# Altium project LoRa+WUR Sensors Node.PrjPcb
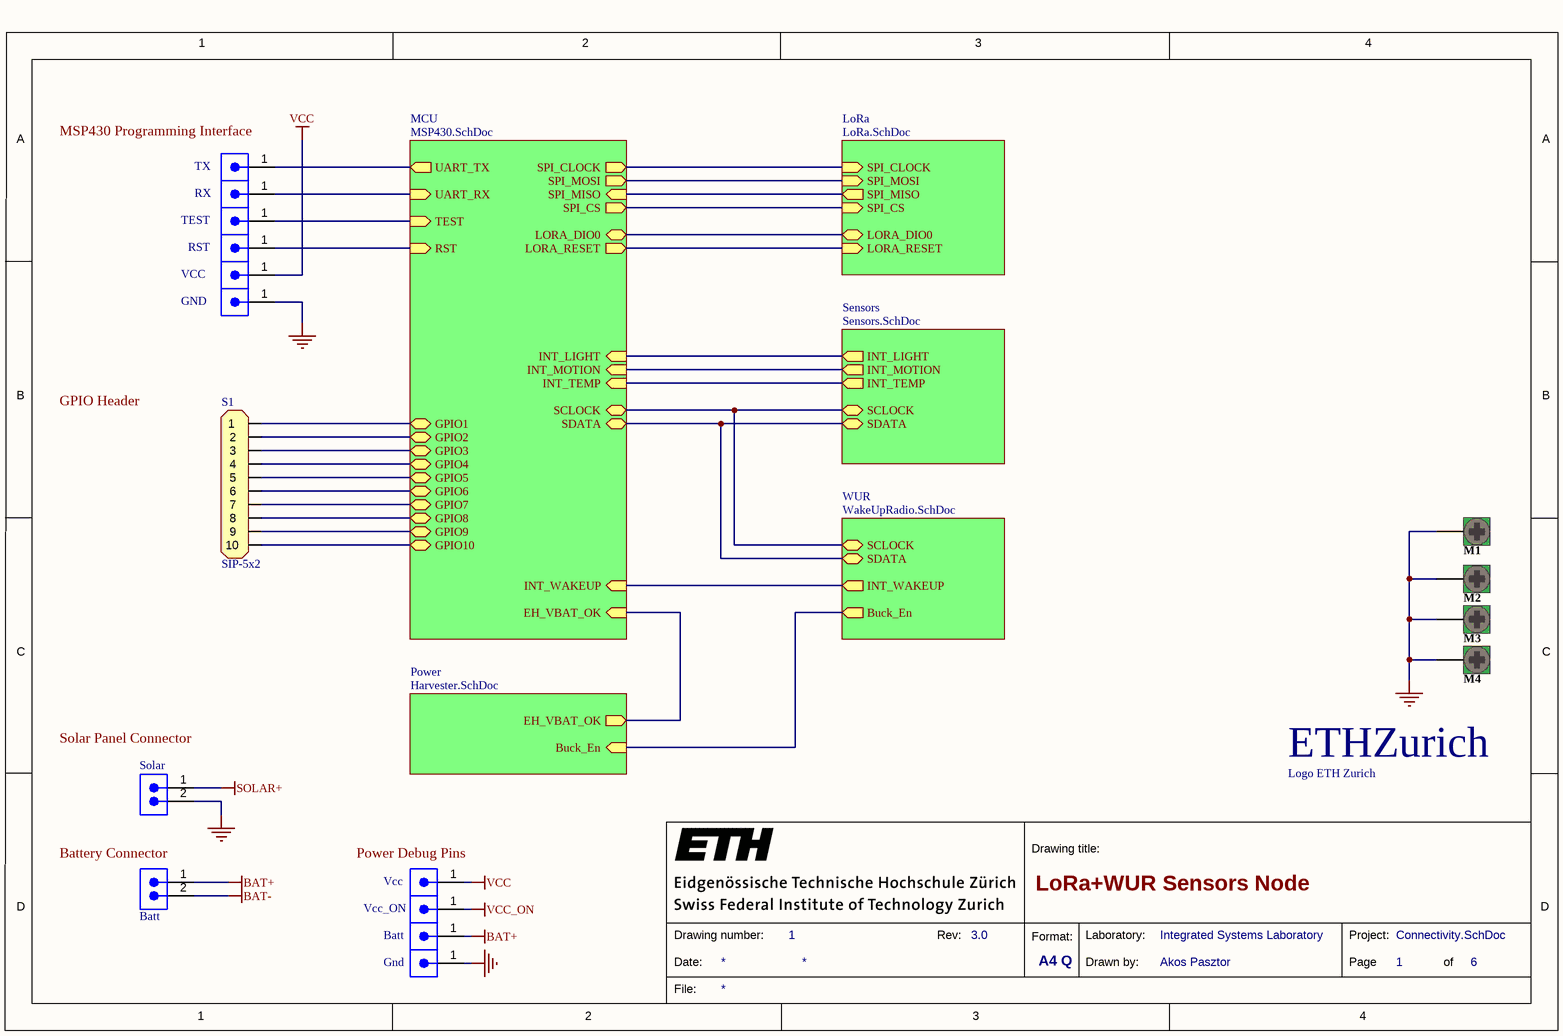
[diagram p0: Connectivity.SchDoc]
Author: Akos Pasztor; CompanyName: ETH Zurich; DrawnBy: Akos Pasztor; Engineer: Akos Pasztor; Organization: Integrated Systems Laboratory; Revision: 3.0; Title: LoRa+WUR Sensors Node
6 sheets, 127 parts. Net scope: hierarchical (ports join the sheet entries above them; power ports are global).
Board file: PCB.PcbDoc
Sheets:
  Connectivity.SchDoc
    MCU = MSP430.SchDoc
    Power = Harvester.SchDoc
    Sensors = Sensors.SchDoc
    WUR = WakeUpRadio.SchDoc
    LoRa = LoRa.SchDoc

## Sheet Connectivity.SchDoc: LoRa+WUR Sensors Node
size A4; Author: Akos Pasztor; CompanyName: ETH Zurich; DrawnBy: Akos Pasztor; Engineer: Akos Pasztor; Organization: Integrated Systems Laboratory; DocumentNumber: 1; Revision: 3.0; SheetNumber: 1; SheetTotal: 6

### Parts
A1  Logo ETH Zurich  [eth-zurich_3mm]  (no BOM)
M1  Mounting Hole  [Hole M3]  (value not drawn)  (no BOM)
M2  Mounting Hole  [Hole M3]  (value not drawn)  (no BOM)
M3  Mounting Hole  [Hole M3]  (value not drawn)  (no BOM)
M4  Mounting Hole  [Hole M3]  (value not drawn)  (no BOM)
S1  SIP-5x2  [SIP-5x2]
X1  TX  [TSW-150-07-G-S]
X2  RX  [TSW-150-07-G-S]
X3  TEST  [TSW-150-07-G-S]
X4  RST  [TSW-150-07-G-S]
X5  VCC  [TSW-150-07-G-S]
X6  GND  [TSW-150-07-G-S]
X7  Batt  [Pin Header, 1x2]
X8  Solar  [Pin Header, 1x2]
X18  Vcc  [TSW-150-07-G-S]
X25  Vcc_ON  [TSW-150-07-G-S]
X27  Batt  [TSW-150-07-G-S]
X28  Gnd  [TSW-150-07-G-S]

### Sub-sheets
LoRa = LoRa.SchDoc: SPI_CLOCK (in), SPI_MOSI (in), SPI_MISO (out), LORA_DIO0 (bidir), LORA_RESET (in), SPI_CS (in)
MCU = MSP430.SchDoc: SPI_CLOCK (out), SPI_MOSI (out), SPI_MISO (in), LORA_DIO0 (bidir), LORA_RESET (out), SPI_CS (out), INT_LIGHT (in), INT_MOTION (in), INT_TEMP (in), SCLOCK (bidir), SDATA (bidir), INT_WAKEUP (in), EH_VBAT_OK (in), UART_TX (out), UART_RX (in), TEST (in), RST (in), GPIO1 (bidir), GPIO2 (bidir), GPIO3 (bidir), GPIO4 (bidir), GPIO5 (bidir), GPIO6 (bidir), GPIO7 (bidir), GPIO8 (bidir), GPIO9 (bidir), GPIO10 (bidir)
Power = Harvester.SchDoc: Buck_En (in), EH_VBAT_OK (out)
Sensors = Sensors.SchDoc: INT_LIGHT (out), INT_MOTION (out), INT_TEMP (out), SCLOCK (bidir), SDATA (bidir)
WUR = WakeUpRadio.SchDoc: SCLOCK (bidir), SDATA (bidir), INT_WAKEUP (out), Buck_En (out)

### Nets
BAT+: X7.1 X27.1
BAT-: X7.2
GND: M1.1 M2.1 M3.1 M4.1 X6.1 X8.2 X28.1
SOLAR+: X8.1
VCC: X5.1 X18.1
VCC_ON: X25.1
Buck_En: sheet Power/Buck_En, sheet WUR/Buck_En
LORA_DIO0: sheet MCU/LORA_DIO0, sheet LoRa/LORA_DIO0
LORA_RESET: sheet MCU/LORA_RESET, sheet LoRa/LORA_RESET
SCLK: sheet MCU/SCLOCK, sheet Sensors/SCLOCK, sheet WUR/SCLOCK
SDATA: sheet MCU/SDATA, sheet Sensors/SDATA, sheet WUR/SDATA
SI: sheet MCU/INT_WAKEUP, sheet WUR/INT_WAKEUP
NetJ1_1: sheet MCU/EH_VBAT_OK, sheet Power/EH_VBAT_OK
NetR17_1: sheet MCU/INT_MOTION, sheet Sensors/INT_MOTION
NetR18_1: sheet MCU/INT_LIGHT, sheet Sensors/INT_LIGHT
NetR22_2: sheet MCU/INT_TEMP, sheet Sensors/INT_TEMP
NetS1_1: S1.1 ; sheet MCU/GPIO1
NetS1_2: S1.2 ; sheet MCU/GPIO2
NetS1_3: S1.3 ; sheet MCU/GPIO3
NetS1_4: S1.4 ; sheet MCU/GPIO4
NetS1_5: S1.5 ; sheet MCU/GPIO5
NetS1_6: S1.6 ; sheet MCU/GPIO6
NetS1_7: S1.7 ; sheet MCU/GPIO7
NetS1_8: S1.8 ; sheet MCU/GPIO8
NetS1_9: S1.9 ; sheet MCU/GPIO9
NetS1_10: S1.10 ; sheet MCU/GPIO10
NetU2_4: sheet MCU/SPI_CS, sheet LoRa/SPI_CS
NetU2_11: sheet MCU/SPI_CLOCK, sheet LoRa/SPI_CLOCK
NetU2_20: X1.1 ; sheet MCU/UART_TX
NetU2_21: X2.1 ; sheet MCU/UART_RX
NetU2_22: X3.1 ; sheet MCU/TEST
NetU2_23: X4.1 ; sheet MCU/RST
NetU2_24: sheet MCU/SPI_MOSI, sheet LoRa/SPI_MOSI
NetU2_25: sheet MCU/SPI_MISO, sheet LoRa/SPI_MISO

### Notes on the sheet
- (near X1) MSP430 Programming Interface
- GPIO Header
- (near X8) Solar Panel Connector
- (near X7) Battery Connector
- (near X18) Power Debug Pins

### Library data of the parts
A1 = CMP-00038-1
M1-M4 = CMP-00023-1: Mounting Hole, 7.2mm pad, 3.2mm plated hole
S1 = SIP-5x2: SIP-5x2 2.54mm 2-row; Pitch: 100mil (2.54mm)
X1-X6 = CMP-00008-1: Terminal Assembly, 1 Pin, Vertical, 2.54mm Pitch, Male; Manufacturer: Samtec
X7 X8 = CMP-00100-1: 2 CONTACT(S), MALE, STRAIGHT TWO PART BOARD CONNECTOR, SOLDER, 2.54mm, 1x2; Manufacturer: Amphenol FCI; Manufacturer Part Number: 68000-102HLF; Connector Type: Header, Unshrouded; Number of Positions: 2; Number of Positions Loaded: All; Pitch: 0.100" (2.54mm)
X18 X25 X27 X28 = CMP-00008-2: Conn Unshrouded Header HDR 1 POS Vertical Solder ST Thru-Hole; Manufacturer: Amphenol FCI; Manufacturer Part Number: 68001-101HLF; Connector Type: Header, Unshrouded; Number of Positions: 1; Number of Positions Loaded: All

## Sheet MSP430.SchDoc: LoRa+WUR Sensors Node
size A4; Author: Akos Pasztor; CompanyName: ETH Zurich; DrawnBy: Akos Pasztor; Engineer: Akos Pasztor; Organization: Integrated Systems Laboratory; DocumentNumber: 1; Revision: 3.0; SheetNumber: 2; SheetTotal: 6
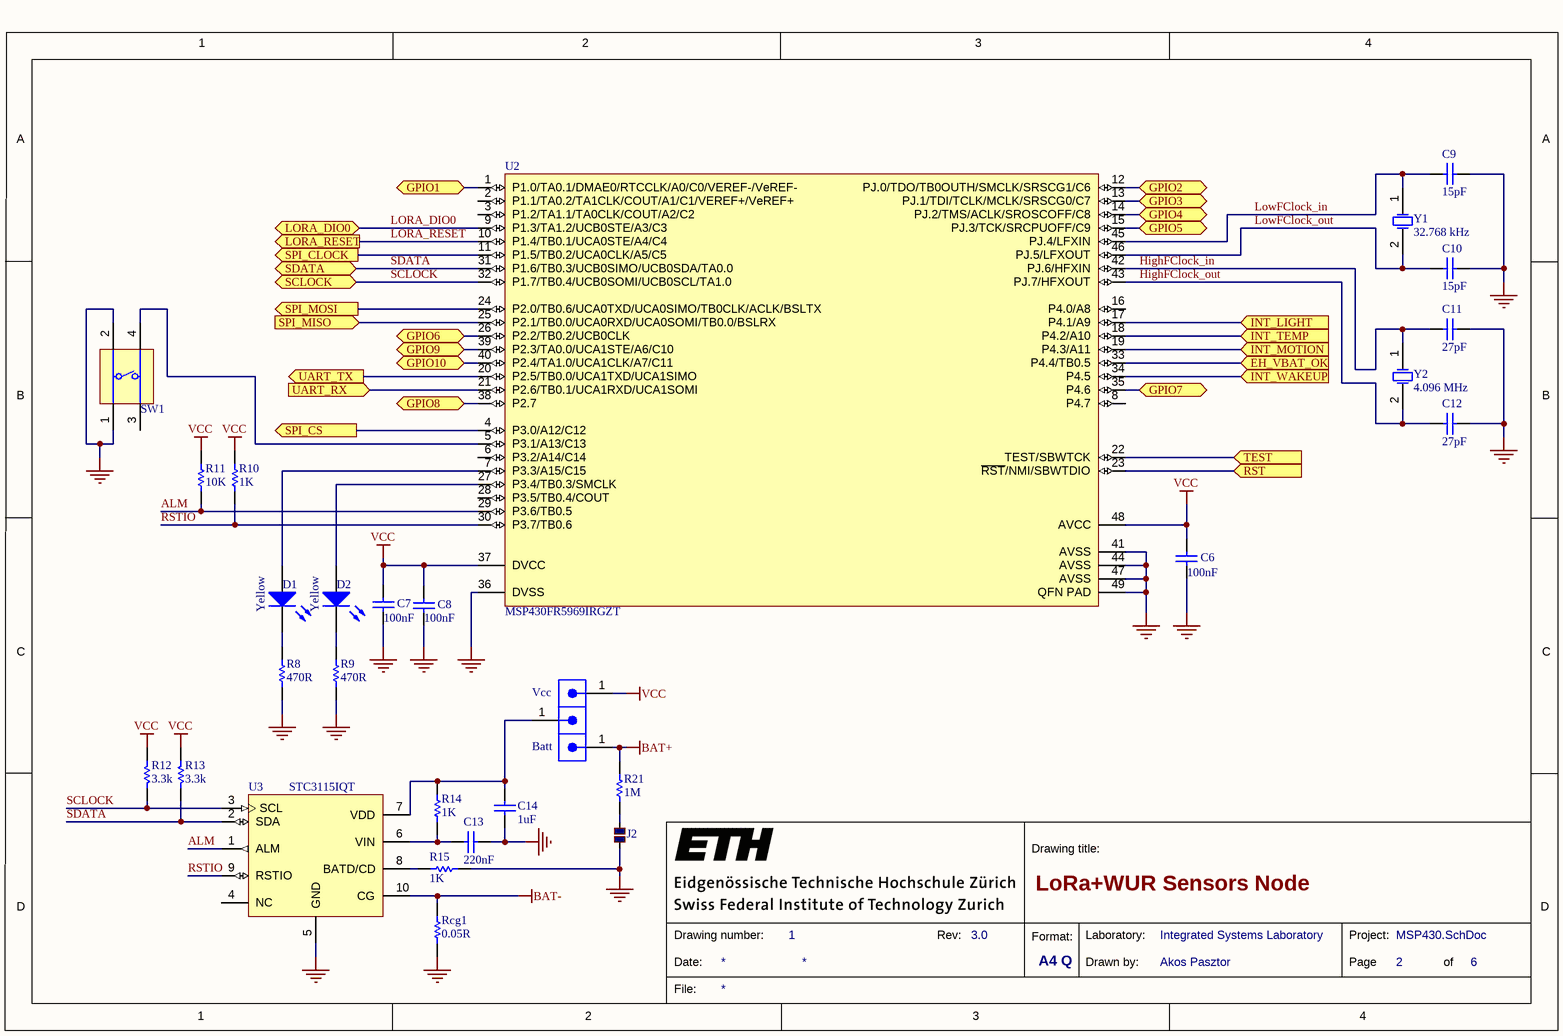
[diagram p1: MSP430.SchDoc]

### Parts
C6  value 100nF  [CAPC0805(2012)145_N]  (hidden comment: CAP 100nF 16V 0805(2012))
C7  value 100nF  [CAPC0805(2012)145_N]  (hidden comment: CAP 100nF 16V 0805(2012))
C8  value 100nF  [CAPC0805(2012)145_N]  (hidden comment: CAP 100nF 16V 0805(2012))
C9  value 15pF  [CAPC0402(1005)60_N]  (hidden comment: CAP 15pF 25V 0402(1005))
C10  value 15pF  [CAPC0402(1005)60_N]  (hidden comment: CAP 15pF 25V 0402(1005))
C11  value 27pF  [CAPC0805(2012)100_N]  (hidden comment: CAP 27pF 10V 0805(2012))
C12  value 27pF  [CAPC0805(2012)100_N]  (hidden comment: CAP 27pF 10V 0805(2012))
C13  value 220nF  [CAPC0805(2012)145_N]  (hidden comment: CAP 220nF 16V 0805(2012))
C14  value 1uF  [CAPC0805(2012)145_N]  (hidden comment: CAP 1uF 16V 0805(2012))
D1  Color: Yellow  [0805_A]  (hidden comment: 150080YS75000)
D2  Color: Yellow  [0805_A]  (hidden comment: 150080YS75000)
J2  Solder Jumper  [Small Solder Jumper]  (value not drawn)
R8  470R  [RESC0603(1608)_N]
R9  470R  [RESC0603(1608)_N]
R10  value 1K  [RESC0805(2012)_N]  (hidden comment: 1K 1% 0805(2012))
R11  value 10K  [RESC0805(2012)_N]  (hidden comment: 10K 1% 0805(2012))
R12  value 3.3k  [RESC0805(2012)_N]  (hidden comment: 3K3 1% 0805(2012))
R13  value 3.3k  [RESC0805(2012)_N]  (hidden comment: 3K3 1% 0805(2012))
R14  value 1K  [RESC0805(2012)_N]  (hidden comment: 1K 1% 0805(2012))
R15  value 1K  [RESC0805(2012)_N]  (hidden comment: 1K 1% 0805(2012))
R21  1M  [RESC0603(1608)_M]
Rcg1  value 0.05R  [RESC0805(2012)_N]  (hidden comment: UCR10EVHFSR050)
SW1  ADTSM62RVTR  [SW_DTSM-62N]  (value not drawn)
U2  MSP430FR5969IRGZT  [QFN-48-7x7-4.1x4.1_N]
U3  STC3115IQT  [SON50P200X60-10N]
X21  Vcc  [TSW-150-07-G-S]
X22  (no value)  [TSW-150-07-G-S]
X23  Batt  [TSW-150-07-G-S]
Y1  Frequency: 32.768 kHz  [ABRA-ABS07-2_V]  (hidden comment: ABS07-32.768KHz-T)
Y2  Frequency: 4.096 MHz  [ABRA-ABLS2-2_V]  (hidden comment: ABLS2-4.096MHZ-D4Y-T)

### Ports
EH_VBAT_OK (in), GPIO1 (bidir), GPIO2 (bidir), GPIO3 (bidir), GPIO4 (bidir), GPIO5 (bidir), GPIO6 (bidir), GPIO7 (bidir), GPIO8 (bidir), GPIO9 (bidir), GPIO10 (bidir), INT_LIGHT (in), INT_MOTION (in), INT_TEMP (in), INT_WAKEUP (in), LORA_DIO0 (bidir), LORA_RESET (out), RST (in), SCLOCK (bidir), SDATA (bidir), SPI_CLOCK (out), SPI_CS (out), SPI_MISO (in), SPI_MOSI (out), TEST (in), UART_RX (in), UART_TX (out)

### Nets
BAT+: R21.1 X23.1
BAT-: Rcg1.2 U3.10(CG)
GND: C6.1 C7.1 C8.1 C9.2 C10.2 C11.1 C12.1 C13.2 C14.1 J2.2 R8.2 R9.2 R15.1 Rcg1.1 SW1.1(T1) SW1.2(T2) U2.36(DVSS) U2.41(AVSS) U2.44(AVSS) U2.47(AVSS) U2.49(QFN_PAD) U3.5(GND)
VCC: C6.2 C7.2 C8.2 R10.1 R11.1 R12.2 R13.2 U2.37(DVCC) U2.48(AVCC) X21.1
ALM: R11.2 U2.29(P3.6/TB0.5) U3.1(ALM)
HighFClock_in: C11.2 U2.42(PJ.6/HFXIN) Y2.1(X1)
HighFClock_out: C12.2 U2.43(PJ.7/HFXOUT) Y2.2(X2)
LORA_DIO0: U2.9(P1.3/TA1.2/UCB0STE/A3/C3) ; port LORA_DIO0
LORA_RESET: U2.10(P1.4/TB0.1/UCA0STE/A4/C4) ; port LORA_RESET
LowFClock_in: C9.1 U2.45(PJ.4/LFXIN) Y1.1(X1)
LowFClock_out: C10.1 U2.46(PJ.5/LFXOUT) Y1.2(X2)
RSTIO: R10.2 U2.30(P3.7/TB0.6) U3.9(RSTIO)
SCLOCK: R12.1 U2.32(P1.7/TB0.4/UCB0SOMI/UCB0SCL/TA1.0) U3.3(SCL) ; port SCLOCK  [project net SCLK]
SDATA: R13.1 U2.31(P1.6/TB0.3/UCB0SIMO/UCB0SDA/TA0.0) U3.2(SDA) ; port SDATA
SI: U2.34(P4.5) ; port INT_WAKEUP
NetC13_1: C13.1 R14.1 U3.6(VIN)
NetC14_2: C14.2 R14.2 U3.7(VDD) X22.1
NetD1_1: D1.1(K) R8.1
NetD1_2: D1.2(A) U2.7(P3.3/A15/C15)
NetD2_1: D2.1(K) R9.1
NetD2_2: D2.2(A) U2.27(P3.4/TB0.3/SMCLK)
NetJ1_1: U2.33(P4.4/TB0.5) ; port EH_VBAT_OK
NetJ2_1: J2.1 R21.2
NetR15_2: R15.2 U3.8(BATD/CD)
NetR17_1: U2.19(P4.3/A11) ; port INT_MOTION
NetR18_1: U2.17(P4.1/A9) ; port INT_LIGHT
NetR22_2: U2.18(P4.2/A10) ; port INT_TEMP
NetS1_1: U2.1(P1.0/TA0.1/DMAE0/RTCCLK/A0/C0/VEREF-/VeREF-) ; port GPIO1
NetS1_2: U2.12(PJ.0/TDO/TB0OUTH/SMCLK/SRSCG1/C6) ; port GPIO2
NetS1_3: U2.13(PJ.1/TDI/TCLK/MCLK/SRSCG0/C7) ; port GPIO3
NetS1_4: U2.14(PJ.2/TMS/ACLK/SROSCOFF/C8) ; port GPIO4
NetS1_5: U2.15(PJ.3/TCK/SRCPUOFF/C9) ; port GPIO5
NetS1_6: U2.26(P2.2/TB0.2/UCB0CLK) ; port GPIO6
NetS1_7: U2.35(P4.6) ; port GPIO7
NetS1_8: U2.38(P2.7) ; port GPIO8
NetS1_9: U2.39(P2.3/TA0.0/UCA1STE/A6/C10) ; port GPIO9
NetS1_10: U2.40(P2.4/TA1.0/UCA1CLK/A7/C11) ; port GPIO10
NetSW1_4: SW1.4(T3) U2.5(P3.1/A13/C13)
NetU2_4: U2.4(P3.0/A12/C12) ; port SPI_CS
NetU2_11: U2.11(P1.5/TB0.2/UCA0CLK/A5/C5) ; port SPI_CLOCK
NetU2_20: U2.20(P2.5/TB0.0/UCA1TXD/UCA1SIMO) ; port UART_TX
NetU2_21: U2.21(P2.6/TB0.1/UCA1RXD/UCA1SOMI) ; port UART_RX
NetU2_22: U2.22(TEST/SBWTCK) ; port TEST
NetU2_23: U2.23(~{RST}/NMI/SBWTDIO) ; port RST
NetU2_24: U2.24(P2.0/TB0.6/UCA0TXD/UCA0SIMO/TB0CLK/ACLK/BSLTX) ; port SPI_MOSI
NetU2_25: U2.25(P2.1/TB0.0/UCA0RXD/UCA0SOMI/TB0.0/BSLRX) ; port SPI_MISO

Not connected (* = marked no-connect by the designer): SW1 3(T3); U2 2(P1.1/TA0.2/TA1CLK/COUT/A1/C1/VEREF+/VeREF+) 3(P1.2/TA1.1/TA0CLK/COUT/A2/C2) 6(P3.2/A14/C14) 8(P4.7) 16(P4.0/A8) 28(P3.5/TB0.4/COUT); U3 4(NC)

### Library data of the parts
C6-C8 = CMP-1036-04401-1: CAP 100nF 16V Â±10% 0805 (2012 Metric) Thickness 1.45mm SMD; Case-Metric: 2012; Case-EIA: 0805
C9 C10 = CMP-1034-00808-1: CAP 15pF 25V ±5% 0402 (1005 Metric) Thickness 0.6mm SMD; Case-Metric: 1005; Case-EIA: 0402; Tolerance: Â±5%
C11 C12 = CMP-1036-01312-1: CAP 27pF 10V ±10% 0805 (2012 Metric) Thickness 1mm SMD; Case-Metric: 2012; Tolerance: Â±10%; Case-EIA: 0805
C13 = CMP-1036-04536-1: CAP 220nF 16V ±20% 0805 (2012 Metric) Thickness 1.45mm SMD; Case-EIA: 0805; Tolerance: Â±20%; Case-Metric: 2012
C14 = CMP-1036-04748-1: CAP 1uF 16V ±20% 0805 (2012 Metric) Thickness 1.45mm SMD; Tolerance: Â±20%; Case-Metric: 2012; Case-EIA: 0805
D1 D2 = CMP-1426-00012-1: SMD mono-color Chip LED, WL-SMCW, Yellow; Manufacturer: Wuerth Elektronik
J2 = CMP-00005-1: Value: 1
R8 R9 = CMP-1012-00066-1: 470R 0.1W 5% 0603 (1608 Metric)  SMD; Case-Metric: 1608; Case-EIA: 0603; Value: 470.00 Ohm
R10 R14 R15 = CMP-1013-00510-1: 1K 0.125W 1% 0805 (2012 Metric)  SMD; Case-Metric: 2012; Case-EIA: 0805
R11 = CMP-1013-00623-1: 10K 0.125W 1% 0805 (2012 Metric)  SMD; Case-Metric: 2012; Case-EIA: 0805
R12 R13 = CMP-1013-00567-1: 3K3 0.125W 1% 0805 (2012 Metric)  SMD; Case-Metric: 2012; Case-EIA: 0805
R21 = CMP-1012-00850-1: 1M02 0.1W 1% 0603 (1608 Metric)  SMD; Case-Metric: 1608; Value: 1020000.00 Ohm; Case-EIA: 0603
Rcg1 = CMP-00129-1: RES SMD 0.05 OHM 1% 1/3W 0805; Manufacturer: Rohm Semiconductor; Resistance (Ohms): 0.05; Power (Watts): 0.333W, 1/3W; Temperature Coefficient: 0/ +150ppm/°C
SW1 = CMP-00033-1: Switch, SPNO Push Button SMD; Manufacturer: APEM; Mechanical Life: 200,000 cycles
U2 = CMP-00055-1: IC MCU 16BIT 64KB FRAM 48VQFN; Manufacturer: Texas Instruments; Core Processor: CPUXV2; Core Size: 16-Bit; Speed: 16MHz; Connectivity: I²C, IrDA, SCI, SPI, UART/USART; Peripherals: Brown-out Detect/Reset, DMA, POR, PWM, WDT; Number of I/O: 40; Program Memory Size: 64KB (64K x 8); RAM Size: 2K x 8; Voltage - Supply (Vcc/Vdd): 1.8 V ~ 3.6 V; Data Converters: A/D 16x12b; Oscillator Type: Internal
U3 = CMP-00128-1: IC GAS GAUGE ALARM OUTPUT 10DFN; Manufacturer: STMicroelectronics; Function: Battery Monitor; Interface: I²C
X21-X23 = CMP-00008-1: as X1 on sheet Connectivity
Y1 = CMP-0447-00001-2: Crystal, 32.768 kHz, 12.5 pF, -40 to 85 degC, SMD Low Profile 3.2 x 1.5 x 0.9 mm, Tape and Reel; Manufacturer: Abracon; Q Value (Type): 30000; Operation Mode: Flexural Mode (Tuning Fork); Shunt Capacitance (C0): 0.9 to 1.2 pF; Load Capacitance (CL): 12.5 pF; Frequency Tolerance @+25degC: +/- 20 ppm; Drive Level (Type): 0.1 uW; Equivalent Series Resistance (R1): 70 Kohm; Insulation Resistance (Min): 500 Mohm
Y2 = CMP-0277-00002-1: Low Profile Surface Mount Microprocessor Crystal, 4.096 MHz +/-30 ppm, 180 Ohm, -40 to 85 degC, 2-Pin 11.4 x 4.7 x 3.3 mm SMD, RoHS, Tape and Reel; Manufacturer: Abracon; Operation Mode: Fundamental or 3rd Overtone; Shunt Capacitance: 7 pF Max.; ESR: 180 Ohm; Load Capacitance: 18 pF

## Sheet Harvester.SchDoc: LoRa+WUR Sensors Node
size A4; Author: Akos Pasztor; CompanyName: ETH Zurich; DrawnBy: Akos Pasztor; Engineer: Akos Pasztor; Organization: Integrated Systems Laboratory; DocumentNumber: 1; Revision: 3.0; SheetNumber: 3; SheetTotal: 6
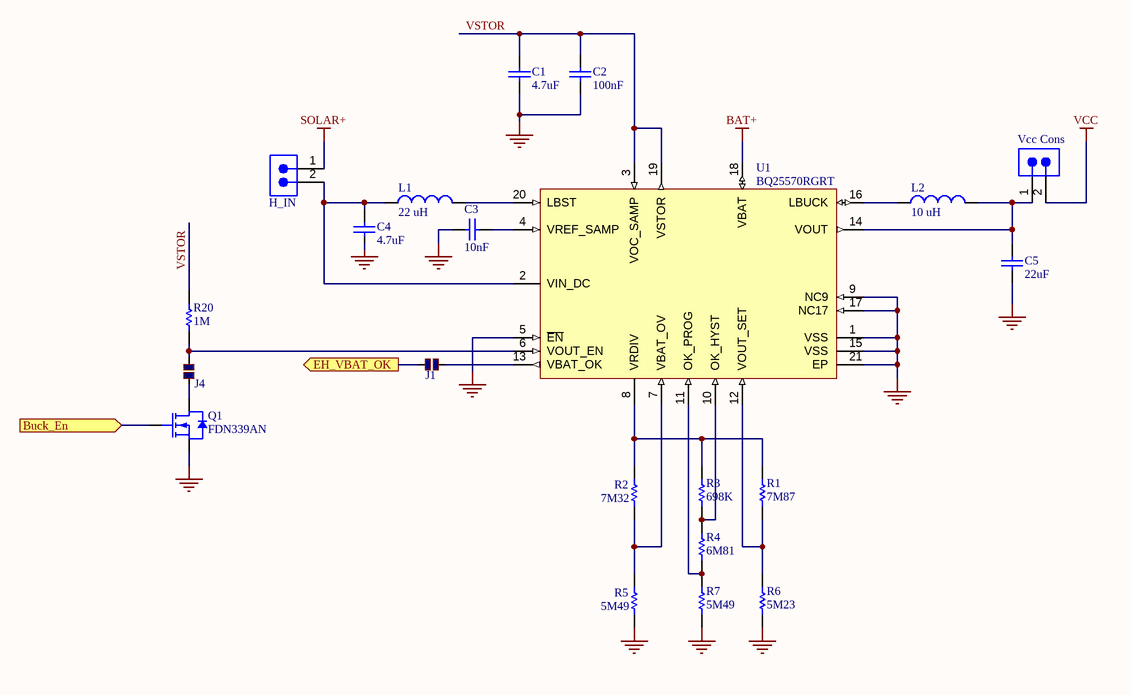
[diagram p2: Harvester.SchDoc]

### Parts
C1  value 4.7uF  [CAPC0402(1005)60_N]  (hidden comment: CAP 4.7uF 6.3V 0402(1005))
C2  value 100nF  [CAPC0402(1005)60_N]  (hidden comment: CAP 100nF 25V 0402(1005))
C3  value 10nF  [CAPC0402(1005)60_N]  (hidden comment: CAP 10nF 25V 0402(1005))
C4  value 4.7uF  [CAPC0402(1005)60_N]  (hidden comment: CAP 4.7uF 6.3V 0402(1005))
C5  value 22uF  [CAPC0805(2012)145_N]  (hidden comment: CAP 22uF 6.3V 0805(2012))
H_IN  H_IN  [Pin Header, 1x2]
J1  Solder Jumper  [Small Solder Jumper]  (value not drawn)
J4  Solder Jumper  [Small Solder Jumper]  (value not drawn)
L1  Inductance: 22 uH  [COILCRAFT-IND-LPS4018]  (hidden comment: LPS4018-223MR)
L2  Inductance: 10 uH  [COILCRAFT-IND-LPS4018]  (hidden comment: LPS4018-103MR)
Q1  FDN339AN  [FDN339AN]
R1  7M87  [RESC0402(1005)_N]
R2  7M32  [RESC0402(1005)_N]
R3  698K  [RESC0402(1005)_M]
R4  6M81  [RESC0402(1005)_M]
R5  5M49  [RESC0402(1005)_N]
R6  5M23  [RESC0402(1005)_N]
R7  5M49  [RESC0402(1005)_N]
R20  1M  [RESC0603(1608)_M]
U1  BQ25570RGRT  [QFN50P350X350X100_HS-21L]
X19  Vcc Cons  [Pin Header, 1x2]

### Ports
Buck_En (in), EH_VBAT_OK (out)

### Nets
BAT+: U1.18(VBAT)
GND: C1.1 C2.1 C3.1 C4.1 C5.1 Q1.2(D) R5.1 R6.1 R7.1 U1.1(VSS) U1.5(~{EN}) U1.9(NC9) U1.15(VSS) U1.17(NC17) U1.21(EP)
SOLAR+: H_IN.1
VCC: X19.2
Buck_En: Q1.1(G) ; port Buck_En
VSTOR: C1.2 C2.2 R20.1 U1.3(VOC_SAMP) U1.19(VSTOR)
NetC3_2: C3.2 U1.4(VREF_SAMP)
NetC4_2: C4.2 H_IN.2 L1.1 U1.2(VIN_DC)
NetC5_2: C5.2 L2.2 U1.14(VOUT) X19.1
NetJ1_1: J1.1 ; port EH_VBAT_OK
NetJ1_2: J1.2 U1.13(VBAT_OK)
NetJ4_1: J4.1 R20.2 U1.6(VOUT_EN)
NetJ4_2: J4.2 Q1.3(D)
NetL1_2: L1.2 U1.20(LBST)
NetL2_1: L2.1 U1.16(LBUCK)
NetR1_1: R1.1 R6.2 U1.12(VOUT_SET)
NetR1_2: R1.2 R2.2 R3.2 U1.8(VRDIV)
NetR2_1: R2.1 R5.2 U1.7(VBAT_OV)
NetR3_1: R3.1 R4.2 U1.10(OK_HYST)
NetR4_1: R4.1 R7.2 U1.11(OK_PROG)

Not connected (* = marked no-connect by the designer): Q1 5(D) 6(D)

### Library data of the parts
C1 C4 = CMP-1034-02136-1: CAP 4.7uF 6.3V ±10% 0402 (1005 Metric) Thickness 0.6mm SMD; Case-EIA: 0402; Tolerance: Â±10%; Case-Metric: 1005
C2 = CMP-1034-02072-1: CAP 100nF 25V ±10% 0402 (1005 Metric) Thickness 0.6mm SMD; Case-EIA: 0402; Tolerance: Â±10%; Case-Metric: 1005
C3 = CMP-1034-01880-1: CAP 10nF 25V ±10% 0402 (1005 Metric) Thickness 0.6mm SMD; Tolerance: Â±10%; Case-Metric: 1005; Case-EIA: 0402
C5 = CMP-1036-04939-1: CAP 22uF 6.3V ±20% 0805 (2012 Metric) Thickness 1.45mm SMD; Case-EIA: 0805; Tolerance: Â±20%; Case-Metric: 2012
H_IN X19 = CMP-00100-1: as X7 on sheet Connectivity
J1 J4 = CMP-00005-1: Value: 1
L1 = CMP-00081-1: Fixed Inductors LPS4018 Low Profile 22uH 0.9A 20% SMD; Core Material: Ferrite; Maximum DC Current: 830 mA; Maximum DC Resistance: 360 mOhms; Self Resonant Frequency: 26 MHz; Shielding: Shielded; Type: Shielded Power Inductor; Brand: Coilcraft; Test Frequency: 100 kHz; P/N: LPS4018-223MRC
L2 = CMP-00083-1: Fixed Inductors LPS4018 Low Profile 10uH 1.25A 20% SMD; Core Material: Ferrite; Maximum DC Current: 1.3 A; Maximum DC Resistance: 200 mOhms; Self Resonant Frequency: 40 MHz; Shielding: Shielded; Type: Shielded Power Inductor; Brand: Coilcraft; Test Frequency: 100 kHz; P/N: LPS4018-103MRB
Q1 = FDN339AN: N-Channel Power MOSFET; Operating Range: -55C to +150C; Rds ON: 0.035Ohm; Drain Current (Cont.): 3A; DrainSource Voltage: 20V; Drain Current (Pulsed): 20A
R1 = CMP-1011-00950-1: 7M87 0.063W 1% 0402 (1005 Metric)  SMD; Value: 7870000.00 Ohm; Case-Metric: 1005; Case-EIA: 0402
R2 = CMP-1011-00947-1: 7M32 0.063W 1% 0402 (1005 Metric)  SMD; Case-Metric: 1005; Case-EIA: 0402; Value: 7.32Meg
R3 = CMP-1011-00832-1: 698K 0.063W 1% 0402 (1005 Metric)  SMD; Value: 698000.00 Ohm; Case-Metric: 1005; Case-EIA: 0402
R4 = CMP-1011-00944-1: 6M81 0.063W 1% 0402 (1005 Metric)  SMD; Value: 6810000.00 Ohm; Case-Metric: 1005; Case-EIA: 0402
R5 = CMP-1011-00933-1: 5M49 0.063W 1% 0402 (1005 Metric)  SMD; Value: 5.49Meg; Case-Metric: 1005; Case-EIA: 0402
R6 = CMP-1011-00931-1: 5M23 0.063W 1% 0402 (1005 Metric)  SMD; Case-EIA: 0402; Case-Metric: 1005; Value: 5230000.00 Ohm
R7 = CMP-1011-00933-1: 5M49 0.063W 1% 0402 (1005 Metric)  SMD; Case-Metric: 1005; Value: 5490000.00 Ohm; Case-EIA: 0402
R20 = CMP-1012-00850-1: as R21 on sheet MSP430
U1 = CMP-00082-2: IC ENERGY HARV CTRLR BATT 20VQFN; Manufacturer: Texas Instruments; Current - Supply: 488nA; Voltage - Supply: 0.12 V ~ 4 V

## Sheet Sensors.SchDoc: LoRa+WUR Sensors Node
size A4; Author: Akos Pasztor; CompanyName: ETH Zurich; DrawnBy: Akos Pasztor; Engineer: Akos Pasztor; Organization: Integrated Systems Laboratory; DocumentNumber: 1; Revision: 3.0; SheetNumber: 5; SheetTotal: 6
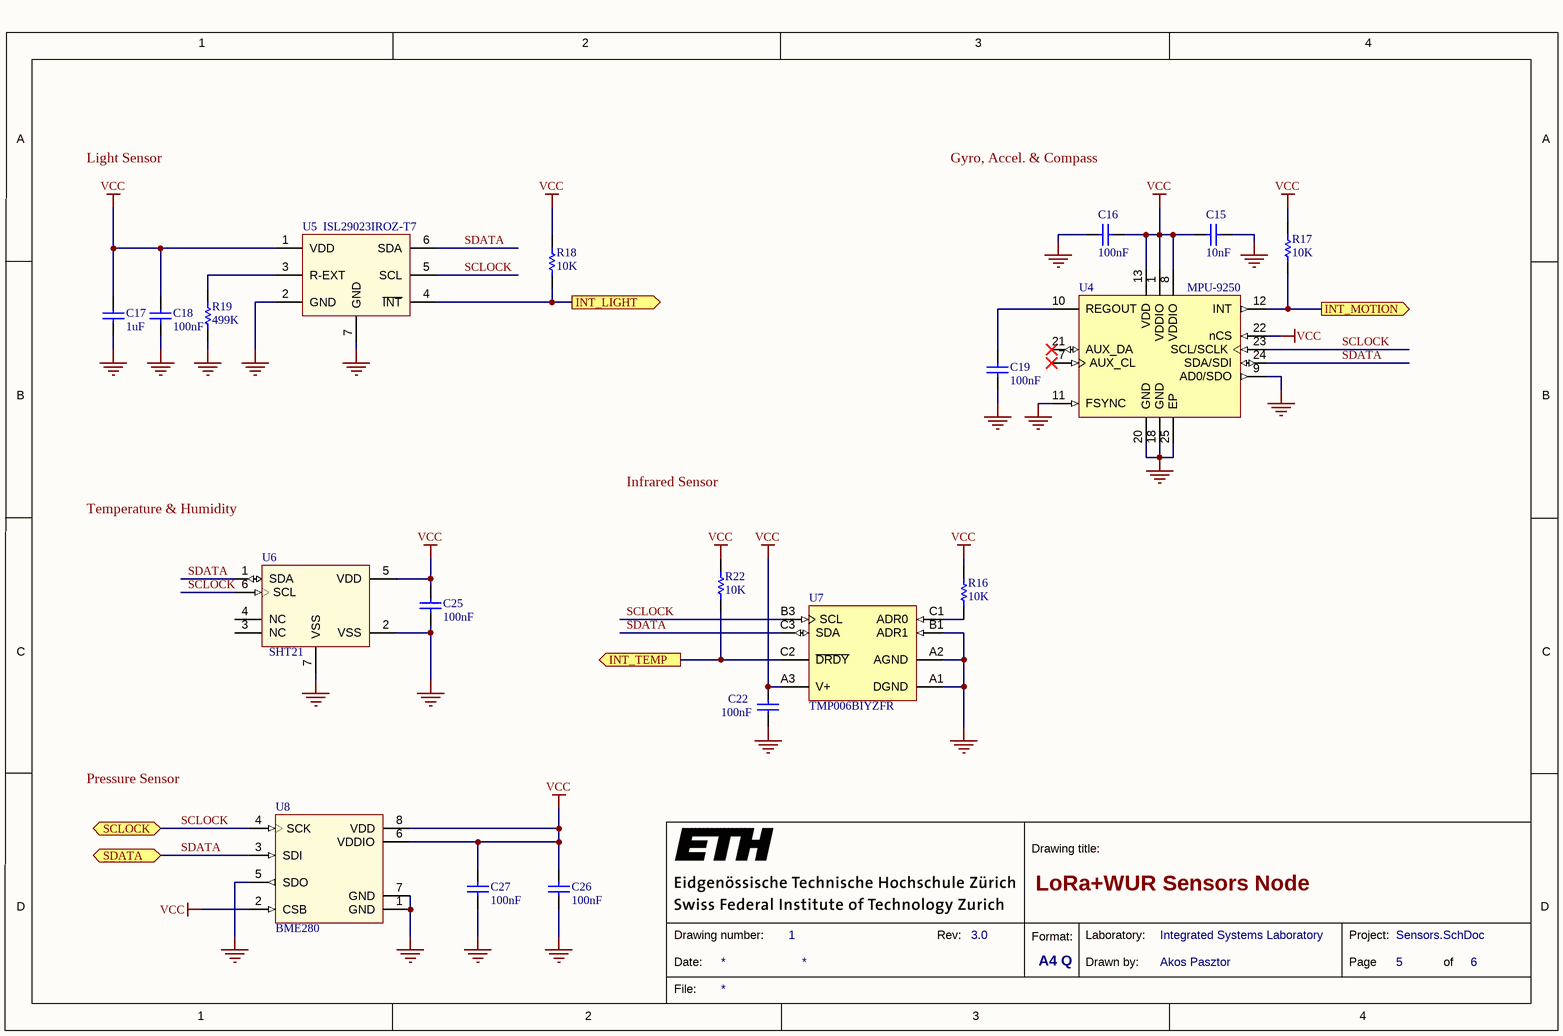
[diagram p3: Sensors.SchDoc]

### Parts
C15  value 10nF  [CAPC0805(2012)100_N]  (hidden comment: CAP 10nF 16V 0805(2012))
C16  value 100nF  [CAPC0805(2012)145_N]  (hidden comment: CAP 100nF 16V 0805(2012))
C17  value 1uF  [CAPC0805(2012)145_N]  (hidden comment: CAP 1uF 16V 0805(2012))
C18  value 100nF  [CAPC0805(2012)145_N]  (hidden comment: CAP 100nF 16V 0805(2012))
C19  value 100nF  [CAPC0805(2012)145_N]  (hidden comment: CAP 100nF 16V 0805(2012))
C22  value 100nF  [CAPC0805(2012)145_N]  (hidden comment: CAP 100nF 16V 0805(2012))
C25  value 100nF  [CAPC0805(2012)145_N]  (hidden comment: CAP 100nF 16V 0805(2012))
C26  value 100nF  [CAPC0805(2012)145_N]  (hidden comment: CAP 100nF 16V 0805(2012))
C27  value 100nF  [CAPC0805(2012)145_N]  (hidden comment: CAP 100nF 16V 0805(2012))
R16  value 10K  [RESC0805(2012)_N]  (hidden comment: 10K 1% 0805(2012))
R17  value 10K  [RESC0805(2012)_N]  (hidden comment: 10K 1% 0805(2012))
R18  value 10K  [RESC0805(2012)_N]  (hidden comment: 10K 1% 0805(2012))
R19  value 499K  [RESC0805(2012)_N]  (hidden comment: 499K 1% 0805(2012))
R22  value 10K  [RESC0805(2012)_N]  (hidden comment: 10K 1% 0805(2012))
U4  MPU-9250  [MPU-9250]
U5  ISL29023IROZ-T7  [SON65P210X75_HS-7N]
U6  SHT21  [SON100P300X110_HS-7N]
U7  TMP006BIYZFR  [YZF0008AHAH]
U8  BME280  [BME280]

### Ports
INT_LIGHT (out), INT_MOTION (out), INT_TEMP (out), SCLOCK (bidir), SDATA (bidir)

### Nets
GND: C15.2 C16.1 C17.1 C18.2 C19.1 C22.2 C25.2 C26.2 C27.2 R19.1 U4.9(AD0/SDO) U4.11(FSYNC) U4.18(GND) U4.20(GND) U4.25(EP) U5.2(GND) U5.7(GND) U6.2(VSS) U6.7(VSS) U7.A1(DGND) U7.A2(AGND) U7.B1(ADR1) U8.1(GND) U8.5(SDO) U8.7(GND)
VCC: C15.1 C16.2 C17.2 C18.1 C22.1 C25.1 C26.1 C27.1 R16.1 R17.2 R18.2 R22.1 U4.1(VDDIO) U4.8(VDDIO) U4.13(VDD) U4.22(nCS) U5.1(VDD) U6.5(VDD) U7.A3(V+) U8.2(CSB) U8.6(VDDIO) U8.8(VDD)
SCLOCK: U4.23(SCL/SCLK) U5.5(SCL) U6.6(SCL) U7.B3(SCL) U8.4(SCK) ; port SCLOCK  [project net SCLK]
SDATA: U4.24(SDA/SDI) U5.6(SDA) U6.1(SDA) U7.C3(SDA) U8.3(SDI) ; port SDATA
NetC19_2: C19.2 U4.10(REGOUT)
NetR16_2: R16.2 U7.C1(ADR0)
NetR17_1: R17.1 U4.12(INT) ; port INT_MOTION
NetR18_1: R18.1 U5.4(~{INT}) ; port INT_LIGHT
NetR19_2: R19.2 U5.3(R-EXT)
NetR22_2: R22.2 U7.C2(~{DRDY}) ; port INT_TEMP

Not connected (* = marked no-connect by the designer): U4 7(AUX_CL)* 21(AUX_DA)*; U6 3(NC) 4(NC)

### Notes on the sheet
- Light Sensor
- Gyro, Accel. & Compass
- Temperature & Humidity
- Infrared Sensor
- Pressure Sensor

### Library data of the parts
C15 = CMP-1036-03818-1: CAP 10nF 16V ±5% 0805 (2012 Metric) Thickness 1mm SMD; Case-Metric: 2012; Case-EIA: 0805; Tolerance: Â±5%
C16 C18 C19 C22 C25-C27 = CMP-1036-04401-1: as C6 on sheet MSP430
C17 = CMP-1036-04748-1: as C14 on sheet MSP430
R16-R18 R22 = CMP-1013-00623-1: as R11 on sheet MSP430
R19 = CMP-1013-00815-1: 499K 0.125W 1% 0805 (2012 Metric)  SMD; Case-Metric: 2012; Case-EIA: 0805
U4 = CMP-00238-1: Accelerometer, Gyroscope, Magnetometer, 3 Axis Sensor I²C, SPI Output; Manufacturer: InvenSense
U5 = CMP-00134-1: INTEGRATED DIGITAL AMBIENT LIGHT SENSOR WITH INTERRUPT FUNCTION, ODFN-6; Manufacturer: Intersil; Wavelength: 540nm; Proximity Detection: No; Output Type: I²C; Voltage - Supply: 2.25 V ~ 3.63 V
U6 = CMP-00136-1: HUMIDITY/TEMPERATURE SENSOR, Accuracy %:2%, Supply Voltage:3V, Humidity Range:0% to 100% Relative Humidity, Sensor Case Style:DFN, No. of Pins:6, Response Time:8s, Operating Temperature Min:-40 C, Operating Temperature Max:125 C , RoHS Compliant; Manufacturer: Sensirion AG; Sensor Type: Humidity, Temperature; Humidity Range: 0 ~ 100% RH; Output Type: I²C; Output: 12V; Accuracy: ±2% RH; Response Time: 8s; Voltage - Supply: 2.1 V ~ 3.6 V
U7 = CMP-0978-00003-2: Infrared Thermopile Sensor, 2.2 to 3.6 V, 240 uA, -40 to 125 degC, 8-Pin BGA (YZF8), Green (RoHS & no Sb/Br), Tape and Reel; Manufacturer: Texas Instruments; Supply Current (Typ): 240 uA; Two-Wire Interface Voltage: 1.8 V; Temp Resolution (Max): 14 Bit
U8 = CMP-00278-1: PRESSURE HUMIDITY TEMP GAS SENS; Manufacturer: Bosch Sensortec; Pressure Type: Vented Gauge; Operating Pressure: 4.35 PSI ~ 15.95 PSI (30 kPa ~ 110 kPa); Output Type: I²C, SPI; Output: 16b; Accuracy: ±0.145 PSI (±1 kPa); Voltage - Supply: 1.71 V ~ 3.6 V; Maximum Pressure: ±290.08 PSI (±2000 kPa)

## Sheet WakeUpRadio.SchDoc: LoRa+WUR Sensors Node
size A4; Author: Akos Pasztor; CompanyName: ETH Zurich; DrawnBy: Akos Pasztor; Engineer: Akos Pasztor; Organization: Integrated Systems Laboratory; DocumentNumber: 1; Revision: 3.0; SheetNumber: 4; SheetTotal: 6
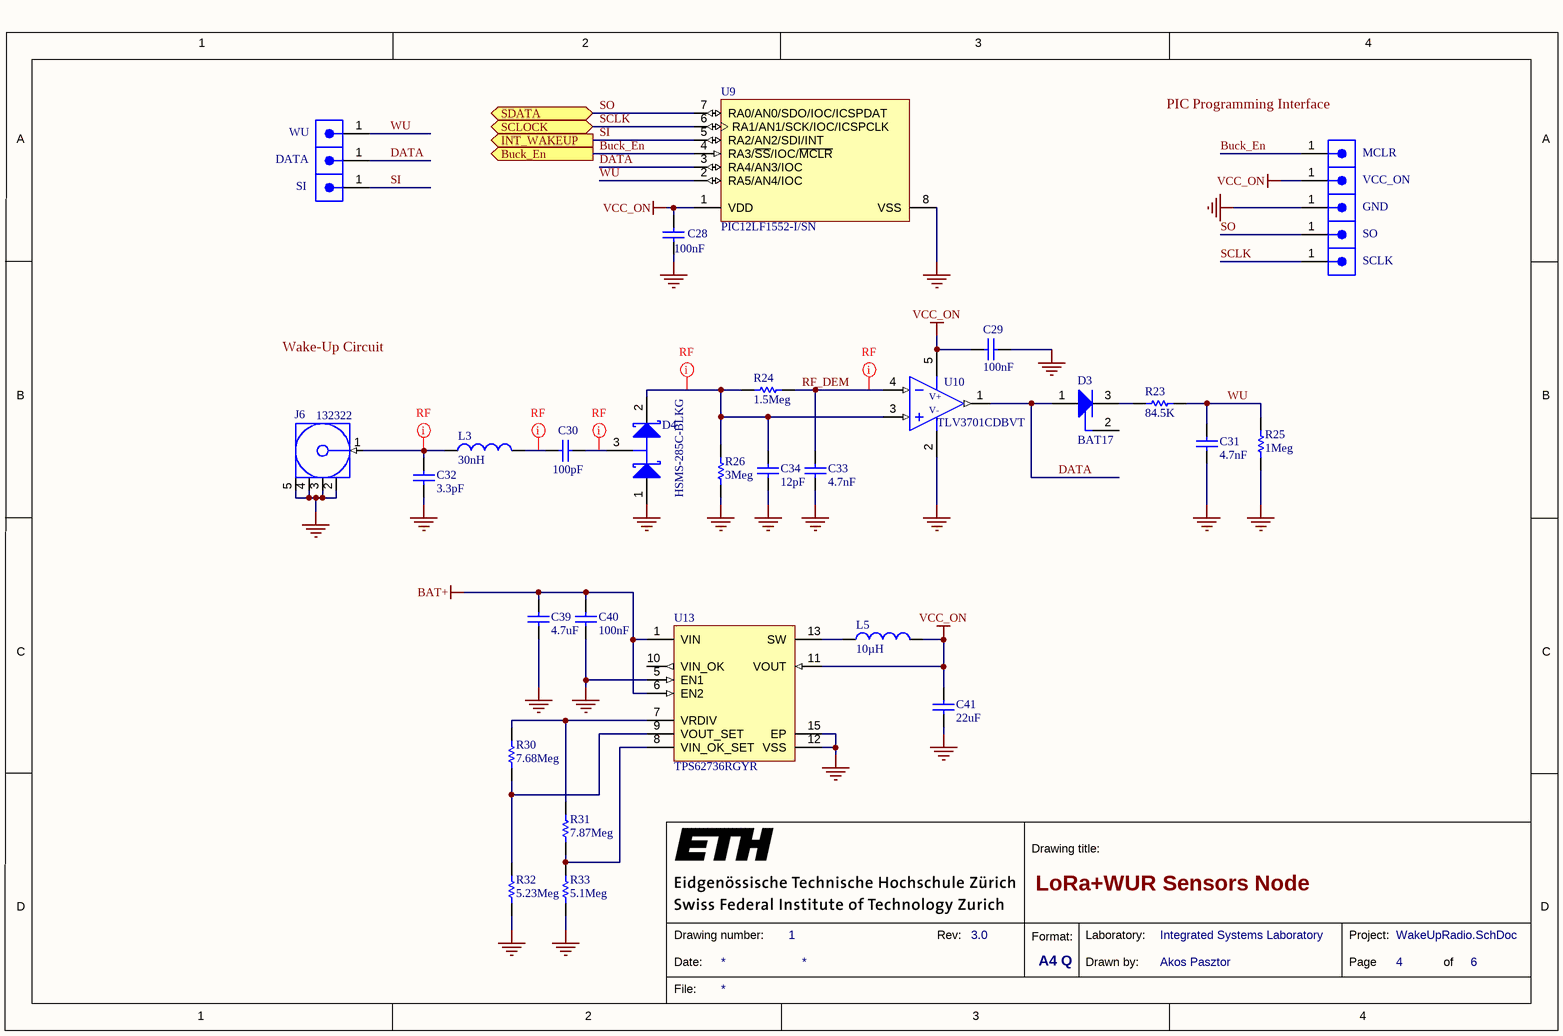
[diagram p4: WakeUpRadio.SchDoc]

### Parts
C28  value 100nF  [CAPC0805(2012)145_N]  (hidden comment: CAP 100nF 16V 0805(2012))
C29  value 100nF  [CAPC0805(2012)145_N]  (hidden comment: CAP 100nF 16V 0805(2012))
C30  value 100pF  [CAPC0805(2012)100_M]  (hidden comment: CAP 100pF 16V 0805(2012))
C31  value 4.7nF  [CAPC0805(2012)145_N]  (hidden comment: CAP 4.7nF 16V 0805(2012))
C32  value 3.3pF  [CAPC0805(2012)75_N]  (hidden comment: CAP 3.3pF 10V 0805(2012))
C33  value 4.7nF  [CAPC0805(2012)145_N]  (hidden comment: CAP 4.7nF 16V 0805(2012))
C34  value 12pF  [CAPC0805(2012)100_N]  (hidden comment: CAP 12pF 25V 0805(2012))
C39  value 4.7uF  [CAPC0402(1005)60_L]  (hidden comment: CAP 4.7uF 6.3V 0402(1005))
C40  value 100nF  [CAPC0402(1005)60_L]  (hidden comment: CAP 100nF 25V 0402(1005))
C41  value 22uF  [CAPC0805(2012)145_N]  (hidden comment: CAP 22uF 6.3V 0805(2012))
D3  BAT17  [INF-SOT23_N]
D4  HSMS-285C-BLKG  [INF-SOT323_N]
J6  132322  [132322]
L3  Inductance: 30nH  [INDC0603(1608)_N]  (hidden comment: LQW18AN30NJ00D)
L5  Inductance: 10µH  [INDC2520X10L]  (hidden comment: 1239AS-H-100M=P2)
R23  value 84.5K  [RESC0805(2012)_N]  (hidden comment: 84K5 1% 0805(2012))
R24  value 1.5Meg  [RESC0805(2012)_N]  (hidden comment: 1M5 1% 0805(2012))
R25  value 1Meg  [RESC0805(2012)_N]  (hidden comment: 1M 1% 0805(2012))
R26  value 3Meg  [RESC0805(2012)_N]  (hidden comment: 3M 1% 0805(2012))
R30  value 7.68Meg  [RESC0402(1005)_L]  (hidden comment: 7M68 1% 0402(1005))
R31  value 7.87Meg  [RESC0402(1005)_L]  (hidden comment: 7M87 1% 0402(1005))
R32  value 5.23Meg  [RESC0402(1005)_L]  (hidden comment: 5M23 1% 0402(1005))
R33  value 5.1Meg  [RESC0402(1005)_N]  (hidden comment: 5M1 1% 0402(1005))
U9  PIC12LF1552-I/SN  [M08A_N]
U10  TLV3701CDBVT  [Z5+1_N]
U13  TPS62736RGYR  [RGY14-2050X2050TP]
X9  WU  [TSW-150-07-G-S]
X10  DATA  [TSW-150-07-G-S]
X11  SI  [TSW-150-07-G-S]
X12  SCLK  [TSW-150-07-G-S]
X13  SO  [TSW-150-07-G-S]
X14  GND  [TSW-150-07-G-S]
X15  VCC_ON  [TSW-150-07-G-S]
X16  MCLR  [TSW-150-07-G-S]

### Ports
Buck_En (out), INT_WAKEUP (out), SCLOCK (bidir), SDATA (bidir)

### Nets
BAT+: C39.2 C40.2 U13.1(VIN) U13.6(EN2)
GND: C28.1 C29.1 C31.1 C32.1 C33.1 C34.1 C39.1 C40.1 C41.1 D4.1(A) J6.2(GND) J6.3(GND) J6.4(GND) J6.5(GND) R25.1 R26.1 R32.1 R33.1 U9.8(VSS) U10.2(V-) U13.5(EN1) U13.12(VSS) U13.15(EP) X14.1
VCC_ON: C28.2 C29.2 C41.2 L5.2 U9.1(VDD) U10.5(V+) U13.11(VOUT) X15.1
Buck_En: U9.4(RA3/~{SS}/IOC/~{MCLR}) X16.1 ; port Buck_En
DATA: D3.1(A) U9.3(RA4/AN3/IOC) U10.1(OUT) X10.1
RF_DEM: C33.2 R24.1 U10.4(-IN)
SCLK: U9.6(RA1/AN1/SCK/IOC/ICSPCLK) X12.1 ; port SCLOCK
SI: U9.5(RA2/AN2/SDI/INT) X11.1 ; port INT_WAKEUP
SO: U9.7(RA0/AN0/SDO/IOC/ICSPDAT) X13.1 ; port SDATA  [project net SDATA]
WU: C31.2 R23.2 R25.2 U9.2(RA5/AN4/IOC) X9.1
NetC30_1: C30.1 D4.3(K/A)
NetC30_2: C30.2 L3.2
NetC32_2: C32.2 J6.1(Signal) L3.1
NetC34_2: C34.2 D4.2(K) R24.2 R26.2 U10.3(+IN)
NetD3_3: D3.3(K) R23.1
NetL5_1: L5.1 U13.13(SW)
NetR30_1: R30.1 R32.2 U13.9(VOUT_SET)
NetR30_2: R30.2 R31.2 U13.7(VRDIV)
NetR31_1: R31.1 R33.2 U13.8(VIN_OK_SET)

Not connected (* = marked no-connect by the designer): D3 2(NC); U13 10(VIN_OK)

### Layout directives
net class RF: NetC30_1, NetC30_2, NetC32_2, NetC34_2, RF_DEM

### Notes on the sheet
- (near X16) PIC Programming Interface
- Wake-Up Circuit

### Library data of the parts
C28 C29 = CMP-1036-04401-1: as C6 on sheet MSP430
C30 = CMP-1036-01943-1: CAP 100pF 16V ±10% 0805 (2012 Metric) Thickness 1mm SMD; Case-Metric: 2012; Case-EIA: 0805; Tolerance: Â±10%
C31 C33 = CMP-1036-03565-1: CAP 4.7nF 16V ±10% 0805 (2012 Metric) Thickness 1.45mm SMD; Tolerance: Â±10%; Case-Metric: 2012; Case-EIA: 0805
C32 = CMP-1036-00386-1: CAP 3.3pF 10V ±0.1pF 0805 (2012 Metric) Thickness 0.75mm SMD; Case-Metric: 2012; Tolerance: Â±0.1pF; Case-EIA: 0805
C34 = CMP-1036-00938-1: CAP 12pF 25V ±5% 0805 (2012 Metric) Thickness 1mm SMD; Case-EIA: 0805; Tolerance: Â±5%; Case-Metric: 2012
C39 = CMP-1034-02136-1: as C1 on sheet Harvester
C40 = CMP-1034-02072-1: as C2 on sheet Harvester
C41 = CMP-1036-04939-1: as C5 on sheet Harvester
D3 = CMP-1154-00014-1: Single Silicon Schottky Diode, 130 mA IF Max, SOT23, Green; Manufacturer: Infineon; VR (max): 4 V; IF (max): 130 mA; CT (typ): 0.55 pF; VF (typ): 0.34 V; Green: yes; Group: RF Mixer
D4 = CMP-00132-1: RF Schottky Diode, Zero Bias, Dual Series, 2 V, 1 mA, 250 mV, 0.3 pF, SOT-323 , RoHS Complian; Manufacturer: Broadcom Limited; Diode Type: Schottky - 1 Pair Series Connection; Voltage - Peak Reverse (Max): 2V; Capacitance @ Vr, F: 0.3pF @ 1V, 1MHz
J6 = CMP-00118-1: CONN SMA JACK 50 OHM EDGE MNT; Manufacturer: Amphenol-RF Division; Connector Type: Jack, Female Socket; Contact Termination: Solder; Impedance: 50 Ohm; Frequency - Max: 18GHz; Body Material: Brass; Body Finish: Gold; Center Contact Material: Beryllium Copper; Dielectric Material: Polytetrafluoroethylene (PTFE)
L3 = CMP-00133-1: FIXED IND 30NH 420MA 230 MOHM 0603; Manufacturer: Murata Electronics North America; Type: Wirewound; Material - Core: Non-Magnetic; Tolerance: ±5%; Shielding: Unshielded; DC Resistance (DCR): 230 mOhm Max; Q @ Freq: 40 @ 250MHz; Frequency - Self Resonant: 3.3GHz; Frequency - Test: 100MHz
L5 = CMP-00241-1: 10µH Shielded Wirewound Inductor 1A 460 mOhm Max 1008 (2520 Metric); Manufacturer: Murata Electronics North America; Material - Core: Powdered Iron; Tolerance: ±20%; Frequency - Test: 1MHz
R23 = CMP-1013-00728-1: 84K5 0.125W 1% 0805 (2012 Metric)  SMD; Case-Metric: 2012; Case-EIA: 0805
R24 = CMP-1013-00867-1: 1M5 0.125W 1% 0805 (2012 Metric)  SMD; Case-Metric: 2012; Case-EIA: 0805
R25 = CMP-1013-00849-1: 1M 0.125W 1% 0805 (2012 Metric)  SMD; Case-Metric: 2012; Case-EIA: 0805
R26 = CMP-1013-00901-1: 3M 0.125W 1% 0805 (2012 Metric)  SMD; Case-Metric: 2012; Case-EIA: 0805
R30 = CMP-1011-00949-1: 7M68 0.063W 1% 0402 (1005 Metric)  SMD; Case-EIA: 0402; Case-Metric: 1005
R31 = CMP-1011-00950-1: 7M87 0.063W 1% 0402 (1005 Metric)  SMD; Case-Metric: 1005; Case-EIA: 0402
R32 = CMP-1011-00931-1: 5M23 0.063W 1% 0402 (1005 Metric)  SMD; Case-Metric: 1005; Case-EIA: 0402
R33 = CMP-1011-00929-1: 5M1 0.063W 1% 0402 (1005 Metric)  SMD; Case-EIA: 0402; Case-Metric: 1005
U9 = CMP-00130-1: IC MCU 8BIT 3.5KB FLASH 8SOIC; Manufacturer: Microchip Technology; Core Processor: PIC; Core Size: 8-Bit; Speed: 32MHz; Connectivity: I²C, SPI; Peripherals: Brown-out Detect/Reset, POR, PWM, WDT; Number of I/O: 5; Program Memory Size: 3.5KB (2K x 14); RAM Size: 256 x 8; Voltage - Supply (Vcc/Vdd): 1.8 V ~ 3.6 V; Data Converters: A/D 4x10b; Oscillator Type: Internal
U10 = CMP-00131-1: IC OUT COMPARATR NANOPWR SOT23-5; Manufacturer: Texas Instruments; Number of Elements: 1; Output Type: CMOS, Push-Pull, Rail-to-Rail; Voltage - Supply, Single/Dual (±): 2.5 V ~ 16 V, ±1.25 V ~ 8 V; Voltage - Input Offset (Max): 5mV @ 15V; Current - Input Bias (Max): 250pA @ 15V; Current - Output (Typ): 10mA; Current - Quiescent (Max): 1µA; CMRR, PSRR (Typ): 88dB CMRR, 105dB PSRR
U13 = CMP-00239-2: Buck Switching Regulator IC Positive Programmable 1.3V 1 Output 50mA 14-VFQFN Exposed Pad; Manufacturer: Texas Instruments; Function: Step-Down; Number of Outputs: 1; Voltage - Input (Min): 2V; Voltage - Input (Max): 5.5V; Voltage - Output (Max): 5V; Frequency - Switching: 2MHz; Synchronous Rectifier: Yes
X9-X16 = CMP-00008-1: as X1 on sheet Connectivity

## Sheet LoRa.SchDoc: LoRa+WUR Sensors Node
size A4; Author: Akos Pasztor; CompanyName: ETH Zurich; DrawnBy: Akos Pasztor; Engineer: Akos Pasztor; Organization: Integrated Systems Laboratory; DocumentNumber: 1; Revision: 3.0; SheetNumber: 6; SheetTotal: 6
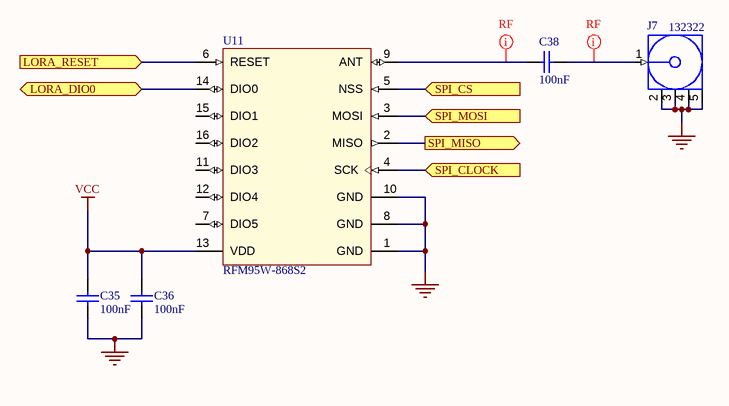
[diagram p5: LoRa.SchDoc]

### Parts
C35  value 100nF  [CAPC0805(2012)145_N]  (hidden comment: CAP 100nF 16V 0805(2012))
C36  value 100nF  [CAPC0805(2012)145_N]  (hidden comment: CAP 100nF 16V 0805(2012))
C38  value 100nF  [CAPC0805(2012)145_N]  (hidden comment: CAP 100nF 16V 0805(2012))
J7  132322  [132322]
U11  RFM95W-868S2  [RFM95W]

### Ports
LORA_DIO0 (bidir), LORA_RESET (in), SPI_CLOCK (in), SPI_CS (in), SPI_MISO (out), SPI_MOSI (in)

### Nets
GND: C35.2 C36.2 J7.2(GND) J7.3(GND) J7.4(GND) J7.5(GND) U11.1(GND) U11.8(GND) U11.10(GND)
VCC: C35.1 C36.1 U11.13(VDD)
LORA_DIO0: U11.14(DIO0) ; port LORA_DIO0
LORA_RESET: U11.6(RESET) ; port LORA_RESET
NetC38_1: C38.1 J7.1(Signal)
NetC38_2: C38.2 U11.9(ANT)
NetU2_4: U11.5(NSS) ; port SPI_CS
NetU2_11: U11.4(SCK) ; port SPI_CLOCK
NetU2_24: U11.3(MOSI) ; port SPI_MOSI
NetU2_25: U11.2(MISO) ; port SPI_MISO

Not connected (* = marked no-connect by the designer): U11 7(DIO5) 11(DIO3) 12(DIO4) 15(DIO1) 16(DIO2)

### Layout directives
net class RF: NetC38_1, NetC38_2

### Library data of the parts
C35 C36 C38 = CMP-1036-04401-1: as C6 on sheet MSP430
J7 = CMP-00118-1: as J6 on sheet WakeUpRadio
U11 = CMP-00138-2: RF TXRX MODULE ISM<1GHZ; Manufacturer: RF Solutions; RF Family/Standard: General ISM < 1GHz; Protocol: LoRa™; Modulation: FSK, GFSK, GMSK, MSK, OOK; Frequency: 868MHz; Data Rate: 300kbps; Power - Output: 17dBm; Sensitivity: -123dBm; Serial Interfaces: SPI; Antenna Type: Not Included; Voltage - Supply: 1.8 V ~ 3.7 V; Current - Receiving: 10.8mA ~ 12.1mA; Current - Transmitting: 20mA ~ 120mA

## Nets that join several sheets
BAT+: Connectivity (X7.1 X27.1), MSP430 (R21.1 X23.1), Harvester (U1.18), WakeUpRadio (C39.2 C40.2 U13.1 U13.6)
BAT-: Connectivity (X7.2), MSP430 (Rcg1.2 U3.10)
GND: Connectivity (7 pins), MSP430 (22 pins), Harvester (15 pins), Sensors (25 pins), WakeUpRadio (24 pins), LoRa (9 pins)
SOLAR+: Connectivity (X8.1), Harvester (H_IN.1)
VCC: Connectivity (X5.1 X18.1), MSP430 (10 pins), Harvester (X19.2), Sensors (22 pins), LoRa (C35.1 C36.1 U11.13)
VCC_ON: Connectivity (X25.1), WakeUpRadio (8 pins)
Buck_En: Harvester (Q1.1), WakeUpRadio (U9.4 X16.1)
LORA_DIO0: MSP430 (U2.9), LoRa (U11.14)
LORA_RESET: MSP430 (U2.10), LoRa (U11.6)
NetJ1_1: MSP430 (U2.33), Harvester (J1.1)
NetR17_1: MSP430 (U2.19), Sensors (R17.1 U4.12)
NetR18_1: MSP430 (U2.17), Sensors (R18.1 U5.4)
NetR22_2: MSP430 (U2.18), Sensors (R22.2 U7.C2)
NetS1_1: Connectivity (S1.1), MSP430 (U2.1)
NetS1_2: Connectivity (S1.2), MSP430 (U2.12)
NetS1_3: Connectivity (S1.3), MSP430 (U2.13)
NetS1_4: Connectivity (S1.4), MSP430 (U2.14)
NetS1_5: Connectivity (S1.5), MSP430 (U2.15)
NetS1_6: Connectivity (S1.6), MSP430 (U2.26)
NetS1_7: Connectivity (S1.7), MSP430 (U2.35)
NetS1_8: Connectivity (S1.8), MSP430 (U2.38)
NetS1_9: Connectivity (S1.9), MSP430 (U2.39)
NetS1_10: Connectivity (S1.10), MSP430 (U2.40)
NetU2_4: MSP430 (U2.4), LoRa (U11.5)
NetU2_11: MSP430 (U2.11), LoRa (U11.4)
NetU2_20: Connectivity (X1.1), MSP430 (U2.20)
NetU2_21: Connectivity (X2.1), MSP430 (U2.21)
NetU2_22: Connectivity (X3.1), MSP430 (U2.22)
NetU2_23: Connectivity (X4.1), MSP430 (U2.23)
NetU2_24: MSP430 (U2.24), LoRa (U11.3)
NetU2_25: MSP430 (U2.25), LoRa (U11.2)
SCLK: MSP430 (R12.1 U2.32 U3.3), Sensors (5 pins), WakeUpRadio (U9.6 X12.1)
SDATA: MSP430 (R13.1 U2.31 U3.2), Sensors (5 pins), WakeUpRadio (U9.7 X13.1)
SI: MSP430 (U2.34), WakeUpRadio (U9.5 X11.1)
